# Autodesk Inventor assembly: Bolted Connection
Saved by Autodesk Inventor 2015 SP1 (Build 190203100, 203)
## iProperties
Created: 2011-06
Part Number: Bolted Connection
Document SubType Name: Assembly
Designer: Guilherme Augusto Franco de Souza
ClientObjectVersion: 1
Author: Guilherme Augusto Franco de Souza
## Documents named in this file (4)
- E:\Visitor Experience Project\WSI2015 - Visitor Experience Project\#46- Sheet Metal Technology\01- 3D Models\Outodoor Heater\2- Assemblies\Outdoor Burner\Design Accelerator\Bolted Connection3.iam
- C:\Users\Guilherme Augusto\Documents\Inventor\Content Center Files\R2015\en-US\ISO 7089\ISO 7089 - 3 - 140 HV(1).ipt
- C:\Users\Guilherme Augusto\Documents\Inventor\Content Center Files\R2015\en-US\ISO 4017(1)\ISO 4017 - M3 x 10ISO.ipt
- C:\Users\Guilherme Augusto\Documents\Inventor\Content Center Files\R2015\en-US\ISO 4032(2)\ISO 4032 - M3ISO.ipt
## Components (8 placed, 3 different names)
1. ISO 7089 3 - 140 HV:5
2. ISO 4017 M3 x 10:3
3. ISO 7089 3 - 140 HV:6
4. ISO 4032 M3:3
5. ISO 4017 M3 x 10:4
6. ISO 7089 3 - 140 HV:7
7. ISO 7089 3 - 140 HV:8
8. ISO 4032 M3:4
